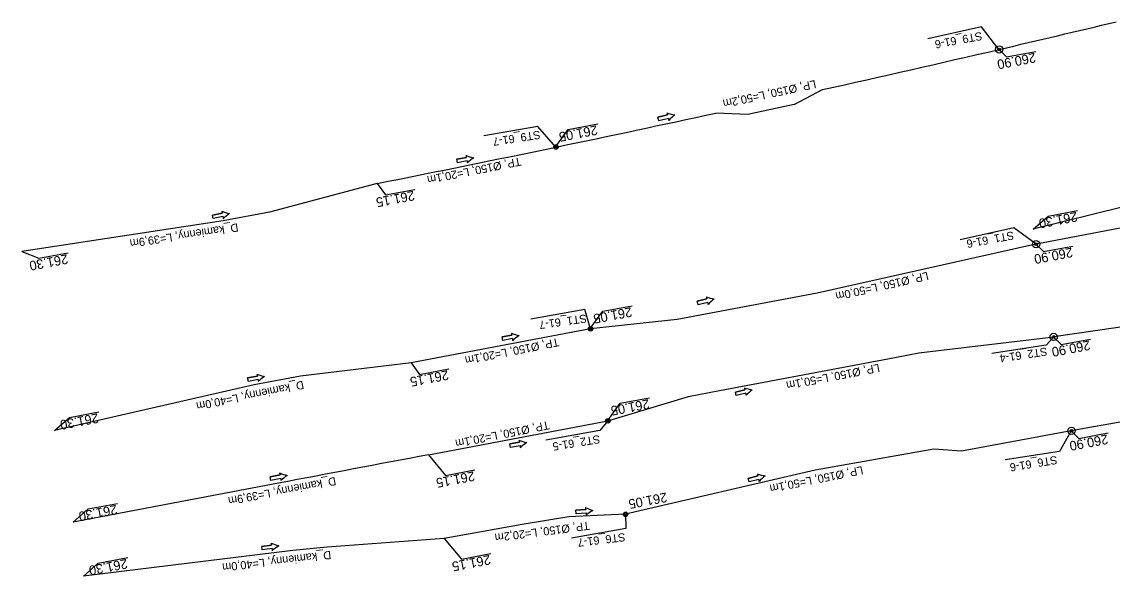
# Model space of a CAD drawing. Extents: x -1 to 65640748, y -22 to 5530284.
# Drawn here: x 6557629.3 to 6557749.5, y 5528700.5 to 5528761.6 of the extents above; entities that cross this region are included whole.
import ezdxf

# ---------------------------------------------------------------- set-up
doc = ezdxf.new("R2010")
doc.units = 0
for name, color, linetype in [('TOR_PROF-studnie i osadniki', 7, 'Continuous'), ('TOR_PS_ODW-drenaze', 7, 'Continuous'), ('TOR_PS_ODW-drenokolektory', 7, 'Continuous'), ('TOR_PS_ODW-studnie PEHD', 7, 'Continuous'), ('TOR_PS_OPIS_O-opisy rurociagow', 7, 'Continuous'), ('TOR_PS_OPIS_O-opisy studni', 7, 'Continuous'), ('TOR_PS_OPIS_T-INFO', 7, 'Continuous')]:
    doc.layers.add(name, color=color, linetype=linetype)

msp = doc.modelspace()

# ---------------------------------------------------------------- linework, layer by layer
at = {"layer": 'TOR_PROF-studnie i osadniki'}
for centre, radius in [((6557688.2, 5528747.81), 0.25), ((6557688.2, 5528747.81), 0.125), ((6557692, 5528727.77), 0.25), ((6557692, 5528727.77), 0.125), ((6557693.92, 5528717.63), 0.25), ((6557693.92, 5528717.63), 0.125), ((6557695.87, 5528707.34), 0.25), ((6557695.87, 5528707.34), 0.125)]:
    msp.add_circle(centre, radius, dxfattribs=at)
at = {"layer": 'TOR_PS_ODW-drenaze'}
msp.add_line((6557657.62, 5528710.77), (6557634.97, 5528706.48), dxfattribs=at)
for points in [[(6557786.46, 5528749.51), (6557773.81, 5528746.9), (6557740.81, 5528738.76)], [(6557668.47, 5528743.79), (6557656.61, 5528740.65), (6557651.5, 5528739.68), (6557629.32, 5528736.29)], [(6557692, 5528727.77), (6557672.22, 5528724.02)], [(6557672.22, 5528724.02), (6557660.04, 5528722.57), (6557654.93, 5528721.61), (6557632.91, 5528716.57)], [(6557674.14, 5528713.9), (6557693.92, 5528717.63)], [(6557695.87, 5528707.34), (6557689.6, 5528707.05), (6557684.47, 5528706.22), (6557675.88, 5528704.68)], [(6557675.88, 5528704.68), (6557662.96, 5528703.73), (6557659.18, 5528703.33), (6557636.1, 5528700.52)]]:
    msp.add_lwpolyline(points, dxfattribs=at)
for centre, radius, start, end in [((6557250.66, 5530849.85), 2147.1, 281.22094, 281.75838), ((6563793.58, 5496340.08), 32947.1, 100.704016, 100.733239)]:
    msp.add_arc(centre, radius, start, end, dxfattribs=at)
at = {"layer": 'TOR_PS_ODW-drenokolektory'}
for p, q in [((6557714.44, 5528752.51), (6557717.58, 5528754.14)), ((6557714.44, 5528752.51), (6557711.9, 5528751.95)), ((6557709.36, 5528751.39), (6557705.82, 5528751.55)), ((6557711.9, 5528751.95), (6557709.36, 5528751.39))]:
    msp.add_line(p, q, dxfattribs=at)
for points in [[(6557806.88, 5528749.54), (6557806.9, 5528749.55), (6557785.22, 5528745.44), (6557781.37, 5528745.73), (6557773.44, 5528744.23), (6557770.08, 5528742.6), (6557741.12, 5528737.11), (6557741.1, 5528737.11)], [(6557808.87, 5528739.14), (6557808.87, 5528739.14), (6557777.59, 5528732.34), (6557767.89, 5528730.5), (6557743.06, 5528726.88)], [(6557741.1, 5528737.11), (6557716.99, 5528731.72), (6557701.56, 5528728.79), (6557692, 5528727.77)], [(6557693.92, 5528717.63), (6557702.82, 5528720.32), (6557706.23, 5528720.97), (6557724.78, 5528724.48), (6557728.19, 5528725.12), (6557743.06, 5528726.88)], [(6557745, 5528716.52), (6557732.89, 5528714.29), (6557729.84, 5528714.51), (6557716.76, 5528712.19), (6557695.87, 5528707.34)]]:
    msp.add_lwpolyline(points, dxfattribs=at)
for centre, radius, start, end in [((6557250.66, 5530849.85), 2147.1, 283.09267, 283.44657), ((6557250.66, 5530849.85), 2147.1, 282.56029, 283.09267), ((6557250.66, 5530849.85), 2147.1, 281.75854, 282.23897), ((6558049.42, 5527026.62), 1717.1, 97.97692, 100.21165)]:
    msp.add_arc(centre, radius, start, end, dxfattribs=at)
at = {"layer": 'TOR_PS_ODW-studnie PEHD'}
for centre, radius in [((6557737.05, 5528758.57), 0.4), ((6557737.05, 5528758.57), 0.145), ((6557688.2, 5528747.81), 0.25), ((6557688.2, 5528747.81), 0.112), ((6557741.12, 5528737.11), 0.4), ((6557741.12, 5528737.11), 0.145), ((6557692, 5528727.77), 0.25), ((6557692, 5528727.77), 0.112), ((6557743.06, 5528726.88), 0.4), ((6557743.06, 5528726.88), 0.145), ((6557693.92, 5528717.63), 0.25), ((6557693.92, 5528717.63), 0.112), ((6557745.02, 5528716.53), 0.4), ((6557745.02, 5528716.53), 0.145), ((6557695.87, 5528707.34), 0.25), ((6557695.87, 5528707.34), 0.112)]:
    msp.add_circle(centre, radius, dxfattribs=at)
at = {"layer": 'TOR_PS_OPIS_O-opisy rurociagow'}
for p, q in [((6557699.44, 5528751.09), (6557700.5, 5528751.36)), ((6557700.5, 5528751.36), (6557699.44, 5528751.09)), ((6557699.54, 5528750.7), (6557699.44, 5528751.09)), ((6557699.54, 5528750.7), (6557699.44, 5528751.09)), ((6557700.6, 5528750.97), (6557699.54, 5528750.7)), ((6557700.6, 5528750.97), (6557699.54, 5528750.7)), ((6557677.27, 5528746.47), (6557678.34, 5528746.67)), ((6557678.34, 5528746.67), (6557677.27, 5528746.47)), ((6557677.34, 5528746.08), (6557677.27, 5528746.47)), ((6557677.34, 5528746.08), (6557677.27, 5528746.47)), ((6557678.41, 5528746.28), (6557677.34, 5528746.08)), ((6557678.41, 5528746.28), (6557677.34, 5528746.08)), ((6557650.35, 5528740.32), (6557651.42, 5528740.53)), ((6557651.42, 5528740.53), (6557650.35, 5528740.32)), ((6557650.42, 5528739.93), (6557650.35, 5528740.32)), ((6557650.42, 5528739.93), (6557650.35, 5528740.32)), ((6557651.49, 5528740.14), (6557650.42, 5528739.93)), ((6557651.49, 5528740.14), (6557650.42, 5528739.93)), ((6557703.78, 5528730.81), (6557704.84, 5528731.07)), ((6557704.84, 5528731.07), (6557703.78, 5528730.81)), ((6557703.88, 5528730.42), (6557703.78, 5528730.81)), ((6557703.88, 5528730.42), (6557703.78, 5528730.81)), ((6557704.94, 5528730.69), (6557703.88, 5528730.42)), ((6557704.94, 5528730.69), (6557703.88, 5528730.42)), ((6557682.26, 5528726.9), (6557683.33, 5528727.09)), ((6557683.33, 5528727.09), (6557682.26, 5528726.9)), ((6557682.33, 5528726.5), (6557682.26, 5528726.9)), ((6557682.33, 5528726.5), (6557682.26, 5528726.9)), ((6557683.41, 5528726.7), (6557682.33, 5528726.5)), ((6557683.41, 5528726.7), (6557682.33, 5528726.5)), ((6557654.21, 5528722.37), (6557655.28, 5528722.57)), ((6557655.28, 5528722.57), (6557654.21, 5528722.37)), ((6557654.29, 5528721.97), (6557654.21, 5528722.37)), ((6557654.29, 5528721.97), (6557654.21, 5528722.37)), ((6557655.36, 5528722.18), (6557654.29, 5528721.97)), ((6557655.36, 5528722.18), (6557654.29, 5528721.97)), ((6557707.97, 5528720.8), (6557709.03, 5528721.07)), ((6557709.03, 5528721.07), (6557707.97, 5528720.8)), ((6557708.07, 5528720.42), (6557707.97, 5528720.8)), ((6557708.07, 5528720.42), (6557707.97, 5528720.8)), ((6557709.13, 5528720.68), (6557708.07, 5528720.42)), ((6557709.13, 5528720.68), (6557708.07, 5528720.42)), ((6557683.1, 5528715.1), (6557684.18, 5528715.3)), ((6557684.18, 5528715.3), (6557683.1, 5528715.1)), ((6557683.18, 5528714.71), (6557683.1, 5528715.1)), ((6557683.18, 5528714.71), (6557683.1, 5528715.1)), ((6557684.25, 5528714.9), (6557683.18, 5528714.71)), ((6557684.25, 5528714.9), (6557683.18, 5528714.71)), ((6557656.71, 5528711.47), (6557657.78, 5528711.67)), ((6557657.78, 5528711.67), (6557656.71, 5528711.47)), ((6557709.4, 5528711.3), (6557710.46, 5528711.56)), ((6557710.46, 5528711.56), (6557709.4, 5528711.3)), ((6557656.78, 5528711.08), (6557656.71, 5528711.47)), ((6557656.78, 5528711.08), (6557656.71, 5528711.47)), ((6557657.86, 5528711.28), (6557656.78, 5528711.08)), ((6557657.86, 5528711.28), (6557656.78, 5528711.08)), ((6557709.5, 5528710.91), (6557709.4, 5528711.3)), ((6557709.5, 5528710.91), (6557709.4, 5528711.3)), ((6557710.56, 5528711.18), (6557709.5, 5528710.91)), ((6557710.56, 5528711.18), (6557709.5, 5528710.91)), ((6557690.4, 5528707.78), (6557691.49, 5528707.88)), ((6557691.49, 5528707.88), (6557690.4, 5528707.78)), ((6557690.44, 5528707.38), (6557690.4, 5528707.78)), ((6557690.44, 5528707.38), (6557690.4, 5528707.78)), ((6557691.52, 5528707.48), (6557690.44, 5528707.38)), ((6557691.52, 5528707.48), (6557690.44, 5528707.38)), ((6557655.77, 5528703.8), (6557656.85, 5528703.95)), ((6557656.85, 5528703.95), (6557655.77, 5528703.8)), ((6557655.82, 5528703.41), (6557655.77, 5528703.8)), ((6557655.82, 5528703.41), (6557655.77, 5528703.8)), ((6557656.91, 5528703.56), (6557655.82, 5528703.41)), ((6557656.91, 5528703.56), (6557655.82, 5528703.41))]:
    msp.add_line(p, q, dxfattribs=at)
for points in [[(6557700.44, 5528751.57), (6557700.44, 5528751.57)], [(6557700.64, 5528750.75), (6557700.64, 5528750.75)], [(6557678.29, 5528746.89), (6557678.29, 5528746.89)], [(6557678.44, 5528746.06), (6557678.44, 5528746.06)], [(6557651.37, 5528740.75), (6557651.37, 5528740.75)], [(6557651.53, 5528739.91), (6557651.53, 5528739.91)], [(6557704.78, 5528731.29), (6557704.78, 5528731.29)], [(6557704.98, 5528730.47), (6557704.98, 5528730.47)], [(6557683.28, 5528727.31), (6557683.28, 5528727.31)], [(6557683.43, 5528726.47), (6557683.43, 5528726.47)], [(6557655.23, 5528722.79), (6557655.23, 5528722.79)], [(6557655.39, 5528721.95), (6557655.39, 5528721.95)], [(6557708.97, 5528721.29), (6557708.97, 5528721.29)], [(6557709.17, 5528720.46), (6557709.17, 5528720.46)], [(6557684.13, 5528715.51), (6557684.13, 5528715.51)], [(6557684.28, 5528714.68), (6557684.28, 5528714.68)], [(6557657.73, 5528711.89), (6557657.73, 5528711.89)], [(6557710.4, 5528711.78), (6557710.4, 5528711.78)], [(6557657.89, 5528711.06), (6557657.89, 5528711.06)], [(6557710.6, 5528710.95), (6557710.6, 5528710.95)], [(6557691.45, 5528708.1), (6557691.45, 5528708.1)], [(6557691.53, 5528707.26), (6557691.53, 5528707.26)], [(6557656.81, 5528704.17), (6557656.81, 5528704.17)], [(6557656.93, 5528703.33), (6557656.93, 5528703.33)]]:
    msp.add_lwpolyline(points, dxfattribs=at)
for centre, radius, start, end in [((6557700.9, 5528751.59), 0.458, 182.433, 210.8942), ((6557702.09, 5528756.2), 4.92, 250.3184, 260.7002), ((6557702.09, 5528756.2), 4.92, 250.3184, 260.7002), ((6557700.9, 5528751.59), 0.458, 182.433, 210.8942), ((6557704.28, 5528747.44), 4.92, 127.3563, 137.7381), ((6557704.28, 5528747.44), 4.92, 127.3563, 137.7381), ((6557701.06, 5528750.95), 0.458, 177.1623, 205.6236), ((6557701.06, 5528750.95), 0.458, 177.1623, 205.6236), ((6557678.74, 5528746.89), 0.458, 179.1379, 207.5992), ((6557680.21, 5528751.42), 4.92, 247.0234, 257.4052), ((6557680.21, 5528751.42), 4.92, 247.0234, 257.4052), ((6557678.74, 5528746.89), 0.458, 179.1379, 207.5992), ((6557681.89, 5528742.55), 4.92, 124.0613, 134.4431), ((6557681.89, 5528742.55), 4.92, 124.0613, 134.4431), ((6557678.87, 5528746.23), 0.458, 173.8673, 202.3285), ((6557678.87, 5528746.23), 0.458, 173.8673, 202.3285), ((6557651.83, 5528740.74), 0.458, 179.1379, 207.5992), ((6557653.29, 5528745.27), 4.92, 247.0234, 257.4052), ((6557653.29, 5528745.27), 4.92, 247.0234, 257.4052), ((6557651.83, 5528740.74), 0.458, 179.1379, 207.5992), ((6557654.97, 5528736.4), 4.92, 124.0613, 134.4431), ((6557654.97, 5528736.4), 4.92, 124.0613, 134.4431), ((6557651.95, 5528740.09), 0.458, 173.8673, 202.3285), ((6557651.95, 5528740.09), 0.458, 173.8673, 202.3285), ((6557705.23, 5528731.31), 0.458, 182.433, 210.8942), ((6557706.43, 5528735.92), 4.92, 250.3184, 260.7002), ((6557706.43, 5528735.92), 4.92, 250.3184, 260.7002), ((6557705.23, 5528731.31), 0.458, 182.433, 210.8942), ((6557708.62, 5528727.16), 4.92, 127.3563, 137.7381), ((6557708.62, 5528727.16), 4.92, 127.3563, 137.7381), ((6557705.39, 5528730.66), 0.458, 177.1623, 205.6236), ((6557705.39, 5528730.66), 0.458, 177.1623, 205.6236), ((6557683.74, 5528727.3), 0.458, 178.6495, 207.1107), ((6557685.24, 5528731.82), 4.92, 246.5349, 256.9167), ((6557685.24, 5528731.82), 4.92, 246.5349, 256.9167), ((6557683.74, 5528727.3), 0.458, 178.6495, 207.1107), ((6557683.86, 5528726.64), 0.458, 173.3788, 201.8401), ((6557683.86, 5528726.64), 0.458, 173.3788, 201.8401), ((6557686.85, 5528722.93), 4.92, 123.5728, 133.9546), ((6557686.85, 5528722.93), 4.92, 123.5728, 133.9546), ((6557655.69, 5528722.78), 0.458, 179.1068, 207.5681), ((6557657.16, 5528727.32), 4.92, 246.9923, 257.3741), ((6557657.16, 5528727.32), 4.92, 246.9923, 257.3741), ((6557655.69, 5528722.78), 0.458, 179.1068, 207.5681), ((6557658.83, 5528718.44), 4.92, 124.0302, 134.412), ((6557658.83, 5528718.44), 4.92, 124.0302, 134.412), ((6557655.81, 5528722.13), 0.458, 173.8362, 202.2974), ((6557655.81, 5528722.13), 0.458, 173.8362, 202.2974), ((6557709.42, 5528721.3), 0.458, 182.433, 210.8942), ((6557710.62, 5528725.92), 4.92, 250.3184, 260.7002), ((6557710.62, 5528725.92), 4.92, 250.3184, 260.7002), ((6557709.42, 5528721.3), 0.458, 182.433, 210.8942), ((6557709.58, 5528720.66), 0.458, 177.1623, 205.6236), ((6557709.58, 5528720.66), 0.458, 177.1623, 205.6236), ((6557712.81, 5528717.15), 4.92, 127.3563, 137.7381), ((6557712.81, 5528717.15), 4.92, 127.3563, 137.7381), ((6557684.59, 5528715.5), 0.458, 178.6495, 207.1107), ((6557686.09, 5528720.03), 4.92, 246.5349, 256.9167), ((6557686.09, 5528720.03), 4.92, 246.5349, 256.9167), ((6557684.59, 5528715.5), 0.458, 178.6495, 207.1107), ((6557687.69, 5528711.14), 4.92, 123.5728, 133.9546), ((6557687.69, 5528711.14), 4.92, 123.5728, 133.9546), ((6557684.71, 5528714.85), 0.458, 173.3788, 201.8401), ((6557684.71, 5528714.85), 0.458, 173.3788, 201.8401), ((6557658.19, 5528711.89), 0.458, 179.1068, 207.5681), ((6557659.65, 5528716.42), 4.92, 246.9923, 257.3741), ((6557659.65, 5528716.42), 4.92, 246.9923, 257.3741), ((6557658.19, 5528711.89), 0.458, 179.1068, 207.5681), ((6557661.33, 5528707.55), 4.92, 124.0302, 134.412), ((6557661.33, 5528707.55), 4.92, 124.0302, 134.412), ((6557710.86, 5528711.8), 0.458, 182.433, 210.8942), ((6557712.06, 5528716.41), 4.92, 250.3184, 260.7002), ((6557712.06, 5528716.41), 4.92, 250.3184, 260.7002), ((6557710.86, 5528711.8), 0.458, 182.433, 210.8942), ((6557714.24, 5528707.65), 4.92, 127.3563, 137.7381), ((6557714.24, 5528707.65), 4.92, 127.3563, 137.7381), ((6557658.31, 5528711.23), 0.458, 173.8362, 202.2974), ((6557658.31, 5528711.23), 0.458, 173.8362, 202.2974), ((6557711.02, 5528711.15), 0.458, 177.1623, 205.6236), ((6557711.02, 5528711.15), 0.458, 177.1623, 205.6236), ((6557691.91, 5528708.05), 0.458, 173.7419, 202.2031), ((6557693.79, 5528712.43), 4.92, 241.6273, 252.0092), ((6557693.79, 5528712.43), 4.92, 241.6273, 252.0092), ((6557691.91, 5528708.05), 0.458, 173.7419, 202.2031), ((6557691.97, 5528707.39), 0.458, 168.4712, 196.9325), ((6557691.97, 5528707.39), 0.458, 168.4712, 196.9325), ((6557694.63, 5528703.44), 4.92, 118.6652, 129.0471), ((6557694.63, 5528703.44), 4.92, 118.6652, 129.0471), ((6557657.27, 5528704.14), 0.458, 176.3157, 204.7769), ((6557658.95, 5528708.6), 4.92, 244.2011, 254.583), ((6557658.95, 5528708.6), 4.92, 244.2011, 254.583), ((6557657.27, 5528704.14), 0.458, 176.3157, 204.7769), ((6557657.36, 5528703.48), 0.458, 171.045, 199.5063), ((6557657.36, 5528703.48), 0.458, 171.045, 199.5063), ((6557660.19, 5528699.66), 4.92, 121.239, 131.6209), ((6557660.19, 5528699.66), 4.92, 121.239, 131.6209)]:
    msp.add_arc(centre, radius, start, end, dxfattribs=at)
at = {"layer": 'TOR_PS_OPIS_T-INFO'}
for points in [[(6557737.03, 5528758.57), (6557735.11, 5528761.04), (6557729.2, 5528759.72)], [(6557737.02, 5528758.58), (6557737.87, 5528757.74), (6557741.11, 5528758.34)], [(6557688.2, 5528747.81), (6557686.21, 5528750.09), (6557680.24, 5528749.03)], [(6557688.18, 5528747.87), (6557689.56, 5528749.75), (6557692.8, 5528750.36)], [(6557668.47, 5528743.79), (6557669.4, 5528742.54), (6557672.64, 5528743.14)], [(6557740.81, 5528738.76), (6557742.46, 5528740.21), (6557745.7, 5528740.82)], [(6557741.12, 5528737.11), (6557738.66, 5528738.91), (6557732.74, 5528737.59)], [(6557741.09, 5528737.12), (6557741.94, 5528736.28), (6557745.18, 5528736.88)], [(6557629.32, 5528736.29), (6557631.19, 5528735.55), (6557634.43, 5528736.15)], [(6557692, 5528727.77), (6557691.38, 5528729.89), (6557685.41, 5528728.83)], [(6557691.98, 5528727.83), (6557693.36, 5528729.72), (6557696.6, 5528730.32)], [(6557743.06, 5528726.88), (6557742.25, 5528725.99), (6557736.25, 5528725.05)], [(6557743.02, 5528726.89), (6557743.88, 5528726.05), (6557747.12, 5528726.65)], [(6557672.22, 5528724.02), (6557673.15, 5528722.76), (6557676.39, 5528723.37)], [(6557693.9, 5528717.69), (6557695.28, 5528719.58), (6557698.52, 5528720.18)], [(6557632.91, 5528716.57), (6557634.57, 5528718.02), (6557637.81, 5528718.63)], [(6557693.92, 5528717.63), (6557693.05, 5528716.57), (6557687.07, 5528715.51)], [(6557745, 5528716.52), (6557743.71, 5528714.27), (6557737.71, 5528713.34)], [(6557744.99, 5528716.54), (6557745.84, 5528715.69), (6557749.08, 5528716.3)], [(6557674.14, 5528713.9), (6557676.02, 5528711.63), (6557679.26, 5528712.23)], [(6557634.97, 5528706.48), (6557636.62, 5528707.93), (6557639.86, 5528708.53)], [(6557695.87, 5528707.34), (6557695.9, 5528705.76), (6557689.92, 5528704.7)], [(6557675.88, 5528704.68), (6557677.77, 5528702.41), (6557681.01, 5528703.01)], [(6557636.1, 5528700.52), (6557637.75, 5528701.97), (6557640.99, 5528702.58)]]:
    msp.add_lwpolyline(points, dxfattribs=at)

# ---------------------------------------------------------------- texts
at = {"layer": 'TOR_PS_OPIS_O-opisy rurociagow'}
for s, rotation, p in [('LP, Ø150, L=50,2m', 192.2403, (6557716.76, 5528755.21)), ('TP, Ø150, L=20,1m', 191.303, (6557684.26, 5528746.67)), ('D_kamienny, L=39,9m', 188.6002, (6557653.11, 5528739.41)), ('LP, Ø150, L=50,0m', 192.7456, (6557729.15, 5528734.07)), ('TP, Ø150, L=20,1m', 191.303, (6557688.43, 5528726.77)), ('LP, Ø150, L=50,1m', 190.9039, (6557723.79, 5528723.93)), ('D_kamienny, L=40,0m', 191.4545, (6557660.31, 5528722.06)), ('TP, Ø150, L=20,1m', 191.303, (6557687.36, 5528717.61)), ('D_kamienny, L=39,9m', 190.655, (6557663.86, 5528711.46)), ('LP, Ø150, L=50,1m', 191.4873, (6557721.95, 5528712.66)), ('TP, Ø150, L=20,2m', 187.3983, (6557691.85, 5528706.54)), ('D_kamienny, L=40,0m', 186.6474, (6557663.36, 5528703.31))]:
    msp.add_text(s, height=0.9, rotation=rotation, dxfattribs=at).set_placement(p)
at = {"layer": 'TOR_PS_OPIS_O-opisy studni'}
for s, rotation, p in [('ST9_61-6', 190.5835, (6557735.09, 5528760.51)), ('ST9_61-7', 188.7807, (6557686.41, 5528749.63)), ('ST1_61-6', 190.5853, (6557738.59, 5528738.53)), ('ST1_61-7', 188.139, (6557691.52, 5528729.38)), ('ST2_61-4', 188.6317, (6557742.28, 5528725.74)), ('ST2_61-5', 189.2743, (6557692.98, 5528716.08)), ('ST6_61-6', 189.3849, (6557743.38, 5528713.79)), ('ST6_61-7', 186.8967, (6557695.79, 5528705.28))]:
    msp.add_text(s, height=0.9, rotation=rotation, dxfattribs=at).set_placement(p)
at = {"layer": 'TOR_PS_OPIS_T-INFO'}
for s, p in [('260.90', (6557740.98, 5528758.2)), ('261.05', (6557692.67, 5528750.21)), ('261.15', (6557672.51, 5528743)), ('261.30', (6557745.57, 5528740.67)), ('261.30', (6557634.3, 5528736.01)), ('260.90', (6557745.05, 5528736.74)), ('261.05', (6557696.47, 5528730.17)), ('260.90', (6557746.99, 5528726.51)), ('261.15', (6557676.26, 5528723.22)), ('261.05', (6557698.39, 5528720.03)), ('261.30', (6557637.68, 5528718.48)), ('260.90', (6557748.95, 5528716.15)), ('261.15', (6557679.13, 5528712.08)), ('261.05', (6557700.34, 5528709.75)), ('261.30', (6557639.73, 5528708.39)), ('261.30', (6557640.86, 5528702.43)), ('261.15', (6557680.88, 5528702.87))]:
    msp.add_text(s, height=1.05, rotation=190.7506, dxfattribs=at).set_placement(p)

doc.saveas('drawing.dxf')
